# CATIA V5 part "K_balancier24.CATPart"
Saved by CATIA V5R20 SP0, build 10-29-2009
Part number: balancier 24
Publications: "demi largeur balancier", "epaisseur pieces", "largeur pneu", "decalage pneu", "Plan.00", "liaison 24/28", "liaison 24/25", "liaison 24/33 sur 24"
Bounding box of the stored display mesh (mm): x -30 to 300, y 290 to 1110, z -50 to 50
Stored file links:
  G:\Khaled_CFAO_2011\SIL\SIL_GR2\mdardier\Khaled\CAD_ThinkMOTION\K_balancier24.CATPart
  G:\Khaled_CFAO_2011\SIL\SIL_GR2\mdardier\Khaled\CAD_ThinkMOTION\K_ass_tandem.CATProduct
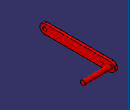
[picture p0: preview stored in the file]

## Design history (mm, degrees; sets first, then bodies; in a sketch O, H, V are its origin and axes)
External parameters (linked from other documents)
  `External.demi largeur balancier` = 50 mm
  `External.epaisseur pieces` = 30 mm
  `External.largeur pneu` = 200 mm
  `External.decalage pneu` = 100 mm
Set1
  Plane1 "Plan.00": linked copy from another document
  Point1 "liaison 24/28": linked copy from another document
  Point2 "liaison 24/25": linked copy from another document
  Point3 "liaison 24/33 sur 24": linked copy from another document
Body1 (main body)
  Sketch1 on Plane1, origin (0, 0, 0), H (0, 1, 0), V (0, 0, 1)
    construction line L1 (340, 0) -> (1060, 0)
    point P1 (340, 0)
    point P2 (1060, 0)
    line L2 (340, 50) -> (1060, 50)
    line L3 (1060, -50) -> (340, -50)
    arc A1 centre (1060, 0) radius 50 from (1060, 50) to (1060, -50) cw
    arc A2 centre (340, 0) radius 50 from (340, -50) to (340, 50) cw
    reference projected point E1 (340, 0) from Point1
    reference projected point E2 (1060, 0) from Point2
    circle A3 centre (340, 0) radius 20
    point P7 (340, 0)
    reference projected point E3 (340, 0) from Point1
    circle A4 centre (975, 0) radius 12.5
    point P8 (975, 0)
    reference projected point E4 (975, 0) from Point3
    distance L1 L2 = 50 {= `External.demi largeur balancier`}
    radius A3 = 20 {= `External.demi largeur balancier` *2/5}
    radius A4 = 12.5 {= `External.demi largeur balancier` /4}
    tangency: A1 L2, A2 L2, A1 L3, A2 L3
    coincidence: P1 E1, P2 E2, P7 E3, P8 E4
  Pad1: profile Sketch1, direction (-1, 0, 0), length 30 {= `External.epaisseur pieces`}
  Sketch2 on start face of Pad1, origin (0, 0, 0), H (0, 1, 0), V (0, 0, 1)
    circle A1 centre (1060, 0) radius 25
    point P1 (1060, 0)
    reference projected point E1 (1060, 0) from Point2
    radius A1 = 25 {= `External.demi largeur balancier` /2}
    coincidence: P1 E1
  Pad2: profile Sketch2, direction (1, 0, 0), length 300 {= `External.largeur pneu` +`External.decalage pneu`}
